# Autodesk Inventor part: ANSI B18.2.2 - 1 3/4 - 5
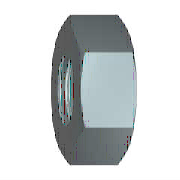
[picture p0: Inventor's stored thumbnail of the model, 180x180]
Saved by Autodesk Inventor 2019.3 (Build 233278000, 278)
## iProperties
Created: 2018-01
Part Number: ANSI B18.2.2 - 1 3/4 - 5
Material: Steel, Mild
Description: Hex Nuts (Inch Series) Heavy Hex Nut
Document SubType Name: Modeling
Standard: ANSI B18.2.2
Designer: u1426
Standard Revision: 2010
Standards Organization: ANSI
Language: en-US
Size Designation: 1 3/4 - 5
Categories: <MemberInstance><Categories><Category DisplayName="Fasteners" InternalName="e4da775c-781d-43d5-af7c-5136215cf5a6" Mnemonic="FSTN"><Category DisplayName="Nuts" I
Density: 7.85 g/cm^3
Appearance: Semi-Polished
IsCustomPart: 0
Author: u1426
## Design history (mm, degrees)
sketch "Sketch1"
  geometry: L1 (-40.328, 0)-(-20.164, 34.925); L2 (-20.164, 34.925)-(20.164, 34.925); L3 (20.164, 34.925)-(40.328, 0); L4 (40.328, 0)-(20.164, -34.925); L5 (20.164, -34.925)-(-20.164, -34.925); L6 (-20.164, -34.925)-(-40.328, 0); 2 further points
  constraints: 12 end point, 1 coincident, 1 horizontal, 11 other
  dimensions: "d0" = 80.65583 distance of L3.end L1.start (= 1.1547 x SW)
extrude "Body" new body sketch "Sketch1" distance "d1" = 43.6626 (= KOH); taper "d2" = 0 deg
sketch "Sketch2"
  geometry: L1 (0, 20.164)-(0, 40.328) reference; L2 (0, 40.328)-(43.663, 40.328) reference; L3 (43.663, 20.164)-(43.663, 40.328) reference; L4 (-8.733, 0)-(52.395, 0) reference; L5 (2.519, 40.328)-(0, 34.925); L6 (41.143, 40.328)-(43.663, 34.925)
  constraints: 4 end point, 4 point on line
  dimensions: "d3" = 25 deg angle of L1 L5 (= ANG1); "d4" = 25 deg angle of L3 L6 (= ANG2); "d5" = 69.85 diameter of L5.end L4 (= SW0); "d6" = 69.85 diameter of L6.end L4 (= SW01)
revolve "Chamfer1" sketch "Sketch2" stored, may be unused: angle "d7" = 90 deg
sketch "Sketch3"
  geometry: A1 r 34.925 centre (0, 0) between (-17.463, -30.246) and (17.463, -30.246) reference; 1 further point
  constraints: 1 coincident
hole "Thread" sketch "Sketch3" at (0, 0) diameter "d25" = 38.9636; stored, may be unused: countersink angle "d29" = 82 deg, drill point angle "d31" = 118 deg; dims "d26" = 6, "d27" = 4, "d28" = 2, "d30" = 8
workaxis "Work Axis1"
workplane "Work Plane1"
body "Solid1"
chamfer "Chamfer2" distance "d8" = 2.74963 (= -0.5 x GD1 + 0.5 x NND); stored, may be unused: angle "d9" = 30 deg, second distance "d40" = 2.74963 (= -0.5 x GD1 + 0.5 x NND)
chamfer "Chamfer3" distance "d10" = 2.74963 (= -0.5 x GD1 + 0.5 x NND); stored, may be unused: angle "d11" = 30 deg, second distance "d41" = 2.74963 (= -0.5 x GD1 + 0.5 x NND)
other parameters: "ANG1" = 25 deg [user parameter; used in 1 equation term], "ANG2" = 25 deg [user parameter; used in 1 equation term], "NND" = 44.45 [user parameter; used in 4 equation terms], "KOH" = 43.6626 [user parameter; used in 1 equation term], "SW" = 69.85 [user parameter; used in 4 equation terms], "SW0" = 69.85 (= SW) [user parameter; used in 1 equation term], "SW01" = 69.85 (= SW) [user parameter; used in 1 equation term], "GD1" = 38.95074 (computed from THREADDIA, PTC, TOA) [user parameter; used in 4 equation terms], "d13" = 0, "d14" = 0, "d39" = 0, "d42" = 0, "THREADDIA" = 44.45 [user parameter; used in 1 equation term], "TOA" = 30 deg [user parameter; used in 1 equation term], "PTC" = 5.08 (computed from TPU) [user parameter; used in 1 equation term], "E0" = 80.67675 (= 1.155 x SW) [user parameter]
